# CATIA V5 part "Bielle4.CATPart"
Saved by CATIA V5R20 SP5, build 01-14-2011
Part number: Bielle4
Bounding box of the stored display mesh (mm): x 10 to 30, y -9.98 to 305.923, z -158.957 to 9.958
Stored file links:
  E:\IAO_2010\iao\IAO_MMS_Groupe2\IAO_MMS_Groupe2\flafosse\Catia\IAO\Bielle4.CATPart
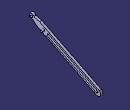
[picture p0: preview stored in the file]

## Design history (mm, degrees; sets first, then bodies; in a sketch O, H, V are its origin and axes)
Body1 (main body)
  Plane1: type Offset, RefPlane yz-plane, Offset 10
  Line1 "Bielle 4": stored without definition
  Sketch1 on Plane1, origin (10, 0, 0), H (0, 1, 0), V (0, 0, 1)
    circle A1 centre (0, 0) radius 5
    arc A2 centre (0, 0) radius 10 from (9.6095, 2.7671) to (3.5614, -9.3443) ccw
    construction line L1 (0, 0) -> (277.4419, -138.5465)
    reference projected line E1 (0, 0) -> (180.1334, -89.9534) from Line1
    construction line L2 (23.939, -25.9263) -> (35.1081, -3.56)
    point P2 (23.939, -25.9263)
    point P3 (35.1081, -3.56)
    line L3 (23.939, -25.9263) -> (3.5614, -9.3443)
    line L4 (35.1081, -3.56) -> (9.6095, 2.7671)
    line L5 (35.1081, -3.56) -> (299.0304, -135.3553)
    line L6 (23.939, -25.9263) -> (287.8613, -157.7216)
    point P7 (23.939, -25.9263)
    arc A3 centre (293.4459, -146.5384) radius 12.5 from (287.8613, -157.7216) to (299.0304, -135.3553) ccw
    point P9 (293.4459, -146.5384)
    point P10 (304.629, -152.123)
    line L7 (72.0167, -30.3743) -> (67.549, -39.3208)
    point P11 (72.0167, -30.3743)
    point P12 (67.549, -39.3208)
    line L8 (72.0167, -30.3743) -> (291.2064, -139.8314)
    line L9 (67.549, -39.3208) -> (286.7388, -148.7779)
    arc A4 centre (288.9726, -144.3046) radius 5 from (291.2064, -139.8314) to (286.7388, -148.7779) cw
    radius A1 = 5
    radius A2 = 10
    distance L2 O = 33
    length L2 = 25
    length L5 = 295
    radius A3 = 12.5
    distance L7 L2 = 45
    length L9 = 245
    length L8 = 245
    coincidence: L1 E1, P7 L3, P7 L2, A3 P10, P10 L1, A4 P9
    perpendicularity: L2 L1
    symmetry: P3 P2 L1, P12 P11 L1
    tangency: L3 A1, L4 A1, A3 L6, L8 A1, A4 L8
    parallelism: L6 L1, L5 L1, L8 L5, L9 L6
  Pad1: profile Sketch1, direction (1, 0, 0), length 10
  Point1 "b": stored without definition
  Sketch2 on end face of Pad1, origin (20, 0, 0), H (0, 1, 0), V (0, 0, 1)
    circle A1 centre (53.0928, -26.513) radius 5
    point P1 (53.0928, -26.513)
    reference projected point E1 (53.0928, -26.513) from Point1
    radius A1 = 5
    coincidence: E1 P1
  Pad2: profile Sketch2, direction (1, 0, 0), length 10
  Plane2: stored without definition
  Plane3: type Offset, RefPlane Plane2, Offset 25
  Point2 "b": stored without definition
  Sketch3 on Plane3, origin (25, 0, 0), H (0, 1, 0), V (0, 0, 1)
    point P1 (53.0928, -26.513)
    reference projected point E1 (53.0928, -26.513) from Point2
    coincidence: P1 E1
  Plane4: stored without definition
  Plane5: type Offset, RefPlane Plane4, Offset 15
  Line2 "Bielle 4": stored without definition
  Sketch4 on Plane5, origin (15, 0, 0), H (0, 1, 0), V (0, 0, 1)
    line L1 (74.2561, -37.0814) -> (288.9726, -144.3046)
    point P1 (74.2561, -37.0814)
    point P2 (288.9726, -144.3046)
    reference projected line E1 (0, 0) -> (180.1334, -89.9534) from Line2
    reference projected arc E2 centre (288.9726, -144.3046) radius 5 from (286.7388, -148.7779) to (291.2064, -139.8314) ccw from edge [end face of Pad1 | face of Pad1 from Sketch1.A4]
    reference projected line E3 (72.0167, -30.3743) -> (67.549, -39.3208) from edge [end face of Pad1 | face of Pad1 from Sketch1.L7]
    distance P1 E3 = 5
    coincidence: L1 E1
    concentricity: P2 E2
  Sketch5 on end face of Pad1, origin (20, 0, 0), H (0, 1, 0), V (0, 0, 1)
    line L1 (69.7829, -34.8476) -> (288.9726, -144.3046)
    point P1 (69.7829, -34.8476)
    point P2 (288.9726, -144.3046)
    reference projected arc E1 centre (288.9726, -144.3046) radius 5 from (286.7388, -148.7779) to (291.2064, -139.8314) ccw from edge [end face of Pad1 | face of Pad1 from Sketch1.A4]
    reference projected line E2 (72.0167, -30.3743) -> (67.549, -39.3208) from edge [end face of Pad1 | face of Pad1 from Sketch1.L7]
    reference projected line E3 (174.9017, -81.7521) -> (72.0167, -30.3743) from edge [end face of Pad1 | face of Pad1 from Sketch1.L8]
    reference projected line E4 (67.549, -39.3208) -> (170.434, -90.6986) from edge [end face of Pad1 | face of Pad1 from Sketch1.L9]
    concentricity: P2 E1
    coincidence: P1 E2
    symmetry: E3 E4 L1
